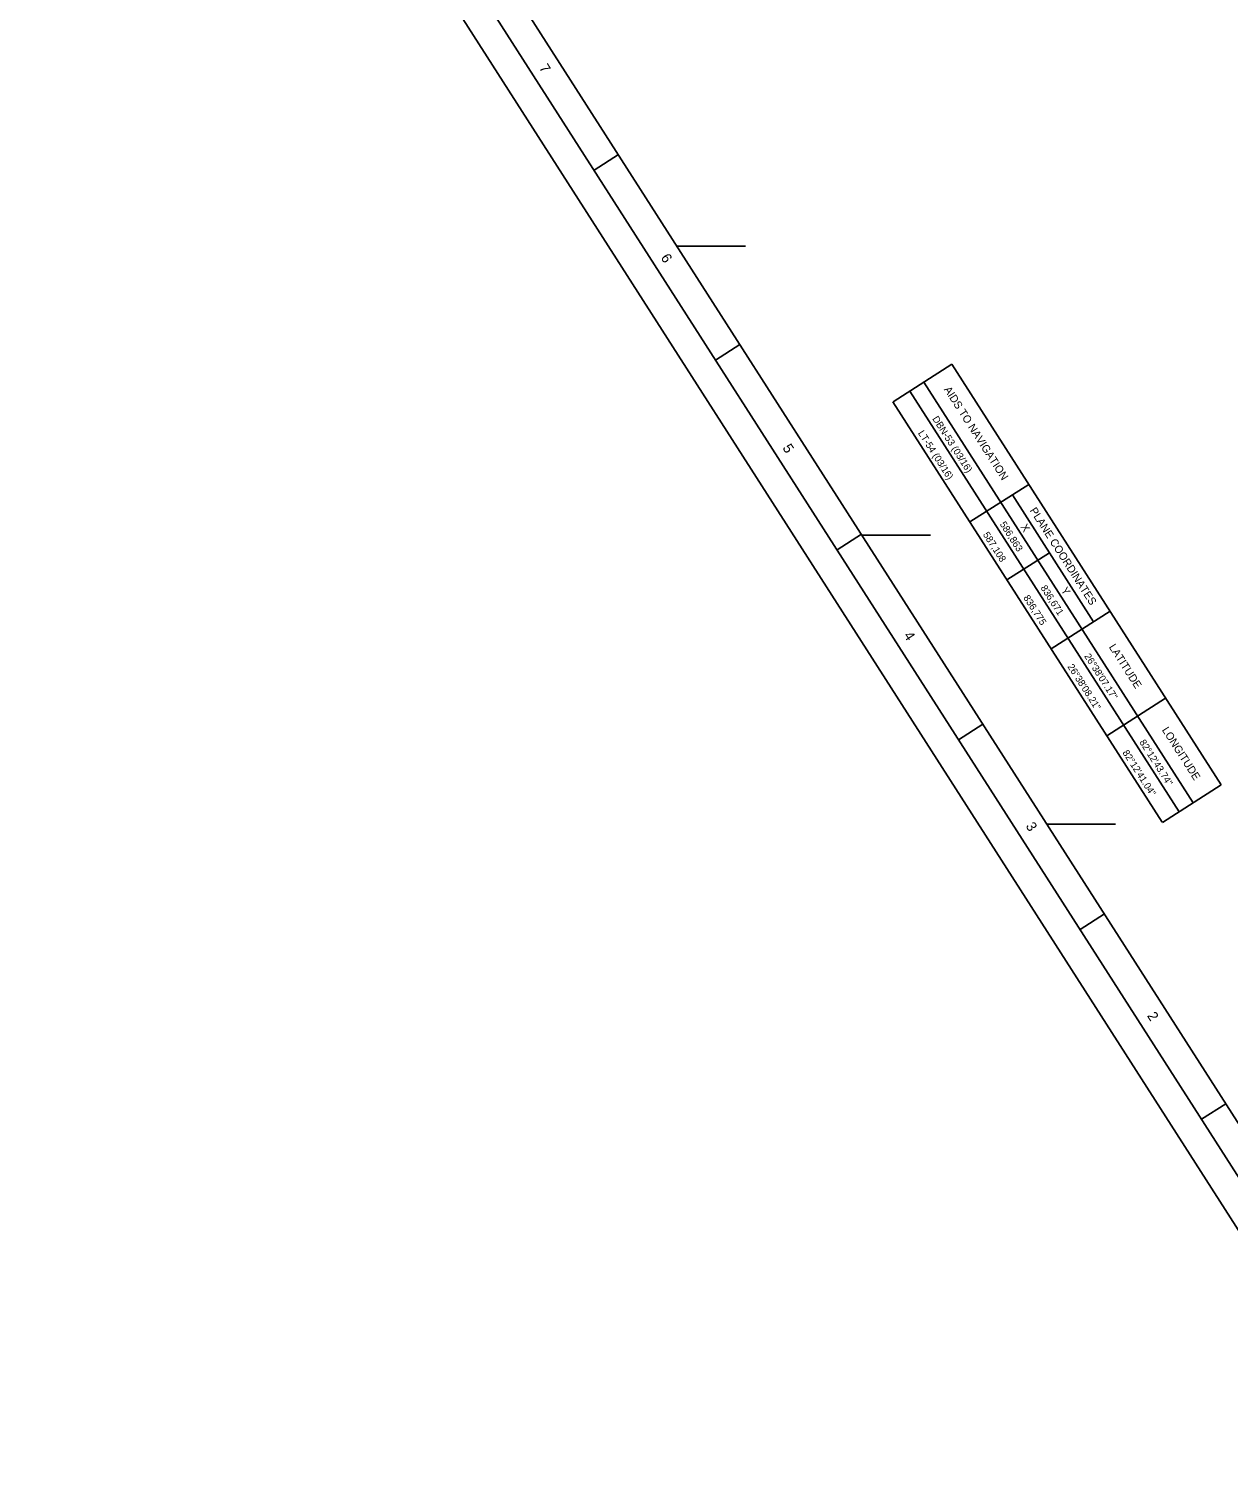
# Model space of a CAD drawing. Extents: x 584499 to 589735, y 833860 to 839399.
# Drawn here: x 584499 to 586575, y 833860 to 836376 of the extents above; entities that cross this region are included whole.
import ezdxf

# ---------------------------------------------------------------- set-up
doc = ezdxf.new("R2010")
doc.units = 0
for name, color, linetype in [('G-ANNO-NPLT', 7, 'Continuous'), ('G-ANNO-TTLB', 7, 'Continuous'), ('V-ANNO-SCHD', 7, 'Continuous'), ('V-ANNO-SYMB', 7, 'Continuous'), ('V-TOPO-COOR-STAT', 7, 'Continuous')]:
    doc.layers.add(name, color=color, linetype=linetype)

msp = doc.modelspace()

# ---------------------------------------------------------------- linework, layer by layer
at = {"layer": 'G-ANNO-NPLT'}
msp.add_lwpolyline([(587362.9, 839398.7), (589735, 835692.9), (586871.4, 833859.9), (584499.3, 837565.7)], close=True, dxfattribs=at)
at = {"layer": 'G-ANNO-TTLB'}
for p, q in [((585476.8, 836131.4), (585518.9, 836158.4)), ((585687, 835803), (585729.1, 835829.9)), ((585897.3, 835474.5), (585939.4, 835501.4)), ((586107.5, 835146), (586149.6, 835173)), ((586317.8, 834817.6), (586359.9, 834844.5)), ((586528, 834489.1), (586570.2, 834516))]:
    msp.add_line(p, q, dxfattribs=at)
for points in [[(584568.4, 837550.6), (586886.5, 833929), (589665.9, 835708.1), (587347.7, 839329.7)], [(589596.8, 835723.2), (587373, 839197.4), (584677.9, 837472.3), (586901.7, 833998.1)]]:
    msp.add_lwpolyline(points, close=True, dxfattribs=at)
at = {"layer": 'V-ANNO-SCHD'}
for p, q in [((586096.1, 835795.6), (585994.3, 835730.4)), ((586096.1, 835795.6), (586561.9, 835067.9)), ((586047.5, 835764.5), (586513.3, 835036.7)), ((586023.1, 835748.9), (586489, 835021.2)), ((585994, 835730.8), (586459.8, 835003.1)), ((586229.1, 835587.8), (586127.2, 835522.7)), ((586200.7, 835569.7), (586341.2, 835350.1)), ((586264.8, 835469.6), (586191.3, 835422.6)), ((586369.6, 835368.3), (586267.8, 835303.1)), ((586465.8, 835218.1), (586363.9, 835152.9)), ((586460.1, 835002.7), (586561.9, 835067.9))]:
    msp.add_line(p, q, dxfattribs=at)
at = {"layer": 'V-TOPO-COOR-STAT'}
for p, q in [((585620.3, 836000), (585739, 836000)), ((585940.3, 835500), (586059.1, 835500)), ((586260.4, 835000), (586379.1, 835000))]:
    msp.add_line(p, q, dxfattribs=at)

# ---------------------------------------------------------------- texts
at = {"layer": 'G-ANNO-TTLB'}
for s, p in [('7', (585381.2, 836308.5)), ('6', (585591.5, 835980.1)), ('5', (585802.2, 835650.9)), ('4', (586011.8, 835326.5)), ('3', (586223, 834996.5)), ('2', (586433.1, 834668.3))]:
    msp.add_text(s, height=17.5, rotation=302.6232, dxfattribs=at).set_placement(p)
at = {"layer": 'V-ANNO-SCHD'}
for s, height, p in [('AIDS TO NAVIGATION', 13.471, (586081.7, 835752)), ('PLANE COORDINATES', 13.471, (586230.1, 835542.6)), ('X', 13.5, (586214.1, 835514)), ('Y', 13.5, (586284, 835404.7)), ('LATITUDE', 13.47, (586367, 835306.4)), ('LONGITUDE', 13.47, (586458.8, 835162.8))]:
    msp.add_text(s, height=height, rotation=302.6233, dxfattribs=at).set_placement(p)
at = {"layer": 'V-ANNO-SYMB'}
for s, p in [('DBN-53 (03/16)', (586061.6, 835701.3)), ('LT-54 (03/16)', (586036.8, 835676.5)), ('586,863', (586178.3, 835518.9)), ('587,108', (586149.2, 835500.9)), ('836,671', (586248.9, 835408.7)), ('836,775', (586219.1, 835391.6)), ('26%%D38\'07.17"', (586324.5, 835290.5)), ('26%%D38\'08.21"', (586295.4, 835272.5)), ('82%%D12\'43.74"', (586419.8, 835141.6)), ('82%%D12\'41.04"', (586390.7, 835123.6))]:
    msp.add_text(s, height=12, rotation=302.6232, dxfattribs=at).set_placement(p)

doc.saveas('drawing.dxf')
